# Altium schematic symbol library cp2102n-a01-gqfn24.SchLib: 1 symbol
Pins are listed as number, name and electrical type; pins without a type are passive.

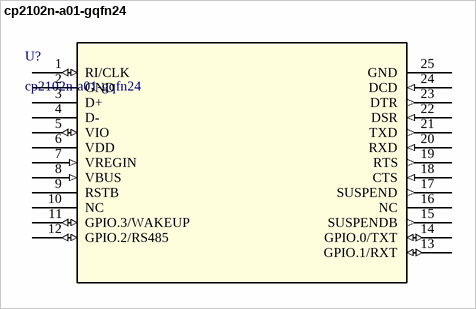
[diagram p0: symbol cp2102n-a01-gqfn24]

## cp2102n-a01-gqfn24
designator U?
No Description Available; Manufacturer_Name: Silicon Labs
footprint QFN24_4X4
pins: 1 RI/CLK (io), 2 GND (power), 3 D+, 4 D-, 5 VIO (io), 6 VDD (power), 7 VREGIN (in), 8 VBUS (in), 9 RSTB, 10 NC, 11 GPIO.3/WAKEUP (io), 12 GPIO.2/RS485 (io), 13 GPIO.1/RXT (io), 14 GPIO.0/TXT (io), 15 SUSPENDB (out), 16 NC, 17 SUSPEND (out), 18 CTS (in), 19 RTS (out), 20 RXD (in), 21 TXD (out), 22 DSR (in), 23 DTR (out), 24 DCD (in), 25 GND (power)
